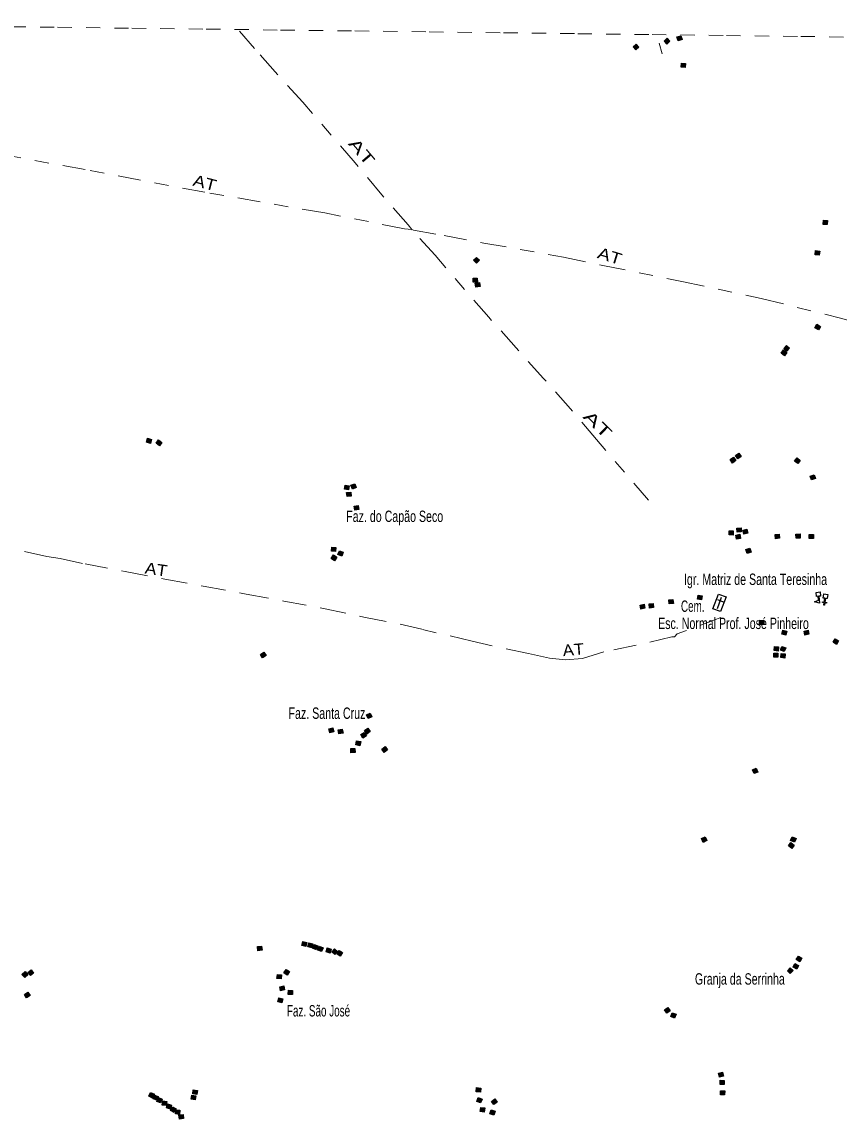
# Model space of a CAD drawing. Extents: x 679 to 705, y 7427.4 to 7455.4.
# Drawn here: x 682.26 to 688.01, y 7447.66 to 7455.38 of the extents above; entities that cross this region are included whole.
import ezdxf
from ezdxf.enums import TextEntityAlignment as Align

# ---------------------------------------------------------------- set-up
doc = ezdxf.new("R2010")
doc.units = 0
doc.header["$LTSCALE"] = 0.032
doc.linetypes.add('DOT_DASHED', pattern=[7.7, 5, -1.2, 0.3, -1.2])
doc.linetypes.add('SHORT_DASHED', pattern=[2.7, 1.5, -1.2])
for name, color, linetype, lineweight in [('2', 7, 'Continuous', 25), ('20', 7, 'Continuous', 25), ('4', 7, 'Continuous', 25), ('51', 7, 'Continuous', 13), ('56', 7, 'DOT_DASHED', 13), ('58', 7, 'SHORT_DASHED', 13), ('6', 7, 'Continuous', 25)]:
    doc.layers.add(name, color=color, linetype=linetype, lineweight=lineweight)
doc.layers.add('61', color=7, linetype='Continuous')

msp = doc.modelspace()

# ---------------------------------------------------------------- hatches: boundary and pattern name
at = {"layer": '2'}
for points in [[(686.9034, 7455.2523), (686.876, 7455.243), (686.8667, 7455.2705), (686.8942, 7455.2798)], [(686.5807, 7455.2205), (686.6, 7455.1989), (686.5783, 7455.1796), (686.559, 7455.2012)], [(686.7985, 7455.2617), (686.8181, 7455.2404), (686.7968, 7455.2207), (686.7771, 7455.2421)], [(686.9275, 7455.0845), (686.9257, 7455.0556), (686.8968, 7455.0573), (686.8985, 7455.0863)], [(687.9276, 7453.9788), (687.9256, 7453.9499), (687.8967, 7453.9519), (687.8987, 7453.9808)], [(685.457, 7453.7197), (685.4775, 7453.6991), (685.457, 7453.6786), (685.4365, 7453.6992)], [(687.8725, 7453.7642), (687.8695, 7453.7353), (687.8407, 7453.7384), (687.8437, 7453.7672)], [(685.4622, 7453.5745), (685.463, 7453.5455), (685.434, 7453.5448), (685.4332, 7453.5738)], [(685.4765, 7453.5433), (685.4814, 7453.5147), (685.4528, 7453.5099), (685.4479, 7453.5384)], [(687.8529, 7453.2493), (687.8778, 7453.2344), (687.8628, 7453.2095), (687.838, 7453.2244)], [(687.6183, 7453.0685), (687.6415, 7453.0511), (687.6241, 7453.0279), (687.6009, 7453.0453)], [(687.6385, 7453.0996), (687.6601, 7453.0802), (687.6407, 7453.0587), (687.6191, 7453.078)], [(683.1418, 7452.4465), (683.1699, 7452.439), (683.1624, 7452.411), (683.1344, 7452.4185)], [(683.2191, 7452.4347), (683.2419, 7452.4169), (683.2241, 7452.394), (683.2012, 7452.4118)], [(687.3033, 7452.3419), (687.3192, 7452.3176), (687.295, 7452.3017), (687.2791, 7452.3259)], [(687.2655, 7452.3132), (687.2824, 7452.2896), (687.2588, 7452.2727), (687.2419, 7452.2963)], [(687.7129, 7452.3091), (687.7355, 7452.2909), (687.7172, 7452.2684), (687.6947, 7452.2866)], [(687.8327, 7452.19), (687.8419, 7452.1625), (687.8143, 7452.1533), (687.8052, 7452.1808)], [(684.5599, 7452.1126), (684.5561, 7452.0838), (684.5274, 7452.0875), (684.5311, 7452.1163)], [(684.5991, 7452.1268), (684.6103, 7452.1), (684.5836, 7452.0888), (684.5723, 7452.1156)], [(684.5708, 7452.0686), (684.5744, 7452.0398), (684.5456, 7452.0362), (684.542, 7452.065)], [(684.6231, 7451.9747), (684.6287, 7451.9462), (684.6003, 7451.9406), (684.5947, 7451.9691)], [(687.2641, 7451.7949), (687.2634, 7451.766), (687.2344, 7451.7667), (687.2351, 7451.7957)], [(687.3185, 7451.8166), (687.3201, 7451.7876), (687.2912, 7451.7861), (687.2896, 7451.815)], [(687.3592, 7451.8061), (687.3654, 7451.7778), (687.3371, 7451.7716), (687.3309, 7451.7999)], [(687.3102, 7451.7709), (687.3158, 7451.7425), (687.2874, 7451.7368), (687.2817, 7451.7652)], [(687.5875, 7451.7717), (687.5901, 7451.7429), (687.5613, 7451.7402), (687.5586, 7451.7691)], [(687.7341, 7451.7734), (687.7357, 7451.7444), (687.7068, 7451.7428), (687.7052, 7451.7718)], [(687.8275, 7451.7706), (687.8275, 7451.7416), (687.7985, 7451.7416), (687.7985, 7451.7706)], [(684.4671, 7451.6784), (684.4639, 7451.6496), (684.435, 7451.6528), (684.4382, 7451.6816)], [(684.4913, 7451.6549), (684.5184, 7451.6444), (684.5079, 7451.6174), (684.4809, 7451.6278)], [(687.3796, 7451.6735), (687.3895, 7451.6463), (687.3623, 7451.6363), (687.3523, 7451.6635)], [(684.4504, 7451.6254), (684.4743, 7451.609), (684.4578, 7451.5851), (684.4339, 7451.6015)], [(687.0443, 7451.3383), (687.0403, 7451.3095), (687.0116, 7451.3135), (687.0156, 7451.3422)], [(686.6357, 7451.2791), (686.6424, 7451.2509), (686.6141, 7451.2443), (686.6075, 7451.2725)], [(686.6996, 7451.2838), (686.7023, 7451.2549), (686.6735, 7451.2522), (686.6708, 7451.2811)], [(686.8394, 7451.3127), (686.8424, 7451.2839), (686.8135, 7451.2809), (686.8105, 7451.3097)], [(687.479, 7451.1649), (687.4783, 7451.1359), (687.4493, 7451.1366), (687.45, 7451.1656)], [(687.6402, 7451.0892), (687.6328, 7451.0612), (687.6047, 7451.0687), (687.6122, 7451.0967)], [(687.7904, 7451.0956), (687.7962, 7451.0672), (687.7678, 7451.0614), (687.762, 7451.0898)], [(687.9804, 7451.0362), (688.0055, 7451.0217), (687.9911, 7450.9966), (687.9659, 7451.011)], [(683.9593, 7450.9419), (683.9753, 7450.9177), (683.9512, 7450.9017), (683.9351, 7450.9258)], [(687.583, 7450.9784), (687.5798, 7450.9496), (687.551, 7450.9527), (687.5541, 7450.9815)], [(687.6327, 7450.9726), (687.6231, 7450.9453), (687.5957, 7450.9549), (687.6054, 7450.9823)], [(687.5772, 7450.9349), (687.5777, 7450.9059), (687.5487, 7450.9054), (687.5482, 7450.9344)], [(687.63, 7450.9293), (687.6275, 7450.9004), (687.5986, 7450.9029), (687.6011, 7450.9318)], [(684.7088, 7450.5122), (684.7206, 7450.4857), (684.6942, 7450.4738), (684.6823, 7450.5003)], [(684.4456, 7450.4086), (684.4526, 7450.3805), (684.4245, 7450.3734), (684.4174, 7450.4016)], [(684.5121, 7450.3999), (684.5172, 7450.3714), (684.4886, 7450.3663), (684.4835, 7450.3948)], [(684.6923, 7450.4062), (684.7091, 7450.3826), (684.6855, 7450.3657), (684.6687, 7450.3893)], [(684.6669, 7450.3771), (684.6815, 7450.3521), (684.6565, 7450.3375), (684.6419, 7450.3625)], [(684.6001, 7450.2644), (684.6016, 7450.2355), (684.5727, 7450.2339), (684.5711, 7450.2629)], [(684.6415, 7450.312), (684.636, 7450.2835), (684.6076, 7450.289), (684.613, 7450.3174)], [(684.8135, 7450.277), (684.8303, 7450.2534), (684.8067, 7450.2365), (684.7899, 7450.2601)], [(687.4258, 7450.125), (687.437, 7450.0982), (687.4102, 7450.087), (687.399, 7450.1138)], [(687.0661, 7449.6419), (687.0786, 7449.6157), (687.0525, 7449.6032), (687.0399, 7449.6294)], [(687.6795, 7449.6432), (687.7059, 7449.6312), (687.6939, 7449.6048), (687.6675, 7449.6167)], [(687.6689, 7449.6011), (687.6924, 7449.5841), (687.6754, 7449.5606), (687.6519, 7449.5776)], [(683.9441, 7448.8729), (683.9471, 7448.844), (683.9183, 7448.841), (683.9153, 7448.8699)], [(684.2342, 7448.9058), (684.2624, 7448.8993), (684.2559, 7448.8711), (684.2276, 7448.8776)], [(684.2765, 7448.8968), (684.3044, 7448.8887), (684.2963, 7448.8609), (684.2685, 7448.869)], [(684.3131, 7448.8848), (684.3402, 7448.8744), (684.3297, 7448.8473), (684.3027, 7448.8578)], [(684.3502, 7448.8723), (684.377, 7448.8612), (684.3659, 7448.8344), (684.3391, 7448.8455)], [(684.4057, 7448.8601), (684.4335, 7448.8521), (684.4255, 7448.8242), (684.3976, 7448.8323)], [(684.4571, 7448.8547), (684.4786, 7448.8352), (684.4591, 7448.8137), (684.4376, 7448.8331)], [(684.4891, 7448.843), (684.5134, 7448.8273), (684.4977, 7448.8029), (684.4733, 7448.8187)], [(687.7225, 7448.803), (687.7473, 7448.7881), (687.7324, 7448.7632), (687.7076, 7448.7781)], [(682.3216, 7448.7062), (682.3394, 7448.6833), (682.3165, 7448.6655), (682.2987, 7448.6884)], [(684.1158, 7448.709), (684.1403, 7448.6935), (684.1248, 7448.669), (684.1003, 7448.6845)], [(687.6646, 7448.7207), (687.6855, 7448.7006), (687.6654, 7448.6797), (687.6445, 7448.6998)], [(687.6969, 7448.7498), (687.723, 7448.7372), (687.7103, 7448.7111), (687.6843, 7448.7238)], [(682.2787, 7448.6935), (682.2982, 7448.6721), (682.2767, 7448.6526), (682.2572, 7448.674)], [(684.0842, 7448.6706), (684.081, 7448.6417), (684.0522, 7448.6449), (684.0554, 7448.6738)], [(682.2983, 7448.5493), (682.3142, 7448.525), (682.2899, 7448.5091), (682.274, 7448.5334)], [(684.1007, 7448.593), (684.106, 7448.5645), (684.0775, 7448.5592), (684.0722, 7448.5877)], [(684.1625, 7448.561), (684.161, 7448.532), (684.132, 7448.5335), (684.1335, 7448.5625)], [(684.0929, 7448.5024), (684.0862, 7448.4742), (684.058, 7448.4808), (684.0646, 7448.5091)], [(686.804, 7448.4409), (686.8205, 7448.4171), (686.7967, 7448.4005), (686.7802, 7448.4243)], [(686.8341, 7448.4042), (686.8612, 7448.3939), (686.8509, 7448.3668), (686.8238, 7448.3772)], [(687.1883, 7447.9855), (687.1956, 7447.9575), (687.1675, 7447.9501), (687.1602, 7447.9782)], [(687.2005, 7447.928), (687.1999, 7447.899), (687.1709, 7447.8997), (687.1715, 7447.9286)], [(683.4633, 7447.8613), (683.4919, 7447.8569), (683.4876, 7447.8283), (683.4589, 7447.8326)], [(685.4864, 7447.8743), (685.4835, 7447.8454), (685.4546, 7447.8483), (685.4575, 7447.8771)], [(687.2037, 7447.8546), (687.2031, 7447.8256), (687.1741, 7447.8263), (687.1747, 7447.8553)], [(683.1889, 7447.8303), (683.1767, 7447.804), (683.1504, 7447.8163), (683.1627, 7447.8425)], [(683.217, 7447.815), (683.2069, 7447.7879), (683.1797, 7447.798), (683.1899, 7447.8252)], [(683.2444, 7447.7957), (683.2327, 7447.7691), (683.2062, 7447.7808), (683.2178, 7447.8073)], [(683.2766, 7447.7798), (683.273, 7447.751), (683.2443, 7447.7546), (683.2478, 7447.7834)], [(683.4529, 7447.8249), (683.4815, 7447.8203), (683.477, 7447.7917), (683.4483, 7447.7963)], [(685.4956, 7447.7963), (685.485, 7447.7694), (685.458, 7447.78), (685.4686, 7447.807)], [(685.5858, 7447.798), (685.603, 7447.7746), (685.5796, 7447.7575), (685.5625, 7447.7808)], [(683.3101, 7447.7542), (683.3019, 7447.7263), (683.2741, 7447.7345), (683.2822, 7447.7623)], [(683.3422, 7447.7269), (683.3278, 7447.7017), (683.3026, 7447.7161), (683.317, 7447.7413)], [(683.3688, 7447.718), (683.3659, 7447.6892), (683.3371, 7447.6921), (683.3399, 7447.7209)], [(685.5157, 7447.7342), (685.5115, 7447.7055), (685.4828, 7447.7097), (685.487, 7447.7384)], [(685.5879, 7447.7111), (685.5786, 7447.6837), (685.5511, 7447.693), (685.5604, 7447.7204)], [(683.3908, 7447.6893), (683.3953, 7447.6606), (683.3667, 7447.6561), (683.3621, 7447.6848)]]:
    msp.add_hatch(color=256, dxfattribs=at).paths.add_polyline_path(points)

# ---------------------------------------------------------------- linework, layer by layer
for points in [[(686.9034, 7455.2523), (686.876, 7455.243), (686.8667, 7455.2705), (686.8942, 7455.2798)], [(686.5807, 7455.2205), (686.6, 7455.1989), (686.5783, 7455.1796), (686.559, 7455.2012)], [(686.7985, 7455.2617), (686.8181, 7455.2404), (686.7968, 7455.2207), (686.7771, 7455.2421)], [(686.9275, 7455.0845), (686.9257, 7455.0556), (686.8968, 7455.0573), (686.8985, 7455.0863)], [(687.9276, 7453.9788), (687.9256, 7453.9499), (687.8967, 7453.9519), (687.8987, 7453.9808)], [(685.457, 7453.7197), (685.4775, 7453.6991), (685.457, 7453.6786), (685.4365, 7453.6992)], [(687.8725, 7453.7642), (687.8695, 7453.7353), (687.8407, 7453.7384), (687.8437, 7453.7672)], [(685.4622, 7453.5745), (685.463, 7453.5455), (685.434, 7453.5448), (685.4332, 7453.5738)], [(685.4765, 7453.5433), (685.4814, 7453.5147), (685.4528, 7453.5099), (685.4479, 7453.5384)], [(687.8529, 7453.2493), (687.8778, 7453.2344), (687.8628, 7453.2095), (687.838, 7453.2244)], [(687.6183, 7453.0685), (687.6415, 7453.0511), (687.6241, 7453.0279), (687.6009, 7453.0453)], [(687.6385, 7453.0996), (687.6601, 7453.0802), (687.6407, 7453.0587), (687.6191, 7453.078)], [(683.1418, 7452.4465), (683.1699, 7452.439), (683.1624, 7452.411), (683.1344, 7452.4185)], [(683.2191, 7452.4347), (683.2419, 7452.4169), (683.2241, 7452.394), (683.2012, 7452.4118)], [(687.3033, 7452.3419), (687.3192, 7452.3176), (687.295, 7452.3017), (687.2791, 7452.3259)], [(687.2655, 7452.3132), (687.2824, 7452.2896), (687.2588, 7452.2727), (687.2419, 7452.2963)], [(687.7129, 7452.3091), (687.7355, 7452.2909), (687.7172, 7452.2684), (687.6947, 7452.2866)], [(687.8327, 7452.19), (687.8419, 7452.1625), (687.8143, 7452.1533), (687.8052, 7452.1808)], [(684.5599, 7452.1126), (684.5561, 7452.0838), (684.5274, 7452.0875), (684.5311, 7452.1163)], [(684.5991, 7452.1268), (684.6103, 7452.1), (684.5836, 7452.0888), (684.5723, 7452.1156)], [(684.5708, 7452.0686), (684.5744, 7452.0398), (684.5456, 7452.0362), (684.542, 7452.065)], [(684.6231, 7451.9747), (684.6287, 7451.9462), (684.6003, 7451.9406), (684.5947, 7451.9691)], [(687.2641, 7451.7949), (687.2634, 7451.766), (687.2344, 7451.7667), (687.2351, 7451.7957)], [(687.3185, 7451.8166), (687.3201, 7451.7876), (687.2912, 7451.7861), (687.2896, 7451.815)], [(687.3592, 7451.8061), (687.3654, 7451.7778), (687.3371, 7451.7716), (687.3309, 7451.7999)], [(687.3102, 7451.7709), (687.3158, 7451.7425), (687.2874, 7451.7368), (687.2817, 7451.7652)], [(687.5875, 7451.7717), (687.5901, 7451.7429), (687.5613, 7451.7402), (687.5586, 7451.7691)], [(687.7341, 7451.7734), (687.7357, 7451.7444), (687.7068, 7451.7428), (687.7052, 7451.7718)], [(687.8275, 7451.7706), (687.8275, 7451.7416), (687.7985, 7451.7416), (687.7985, 7451.7706)], [(684.4671, 7451.6784), (684.4639, 7451.6496), (684.435, 7451.6528), (684.4382, 7451.6816)], [(684.4913, 7451.6549), (684.5184, 7451.6444), (684.5079, 7451.6174), (684.4809, 7451.6278)], [(687.3796, 7451.6735), (687.3895, 7451.6463), (687.3623, 7451.6363), (687.3523, 7451.6635)], [(684.4504, 7451.6254), (684.4743, 7451.609), (684.4578, 7451.5851), (684.4339, 7451.6015)], [(687.0443, 7451.3383), (687.0403, 7451.3095), (687.0116, 7451.3135), (687.0156, 7451.3422)], [(686.6357, 7451.2791), (686.6424, 7451.2509), (686.6141, 7451.2443), (686.6075, 7451.2725)], [(686.6996, 7451.2838), (686.7023, 7451.2549), (686.6735, 7451.2522), (686.6708, 7451.2811)], [(686.8394, 7451.3127), (686.8424, 7451.2839), (686.8135, 7451.2809), (686.8105, 7451.3097)], [(687.479, 7451.1649), (687.4783, 7451.1359), (687.4493, 7451.1366), (687.45, 7451.1656)], [(687.6402, 7451.0892), (687.6328, 7451.0612), (687.6047, 7451.0687), (687.6122, 7451.0967)], [(687.7904, 7451.0956), (687.7962, 7451.0672), (687.7678, 7451.0614), (687.762, 7451.0898)], [(687.9804, 7451.0362), (688.0055, 7451.0217), (687.9911, 7450.9966), (687.9659, 7451.011)], [(683.9593, 7450.9419), (683.9753, 7450.9177), (683.9512, 7450.9017), (683.9351, 7450.9258)], [(687.583, 7450.9784), (687.5798, 7450.9496), (687.551, 7450.9527), (687.5541, 7450.9815)], [(687.6327, 7450.9726), (687.6231, 7450.9453), (687.5957, 7450.9549), (687.6054, 7450.9823)], [(687.5772, 7450.9349), (687.5777, 7450.9059), (687.5487, 7450.9054), (687.5482, 7450.9344)], [(687.63, 7450.9293), (687.6275, 7450.9004), (687.5986, 7450.9029), (687.6011, 7450.9318)], [(684.7088, 7450.5122), (684.7206, 7450.4857), (684.6942, 7450.4738), (684.6823, 7450.5003)], [(684.4456, 7450.4086), (684.4526, 7450.3805), (684.4245, 7450.3734), (684.4174, 7450.4016)], [(684.5121, 7450.3999), (684.5172, 7450.3714), (684.4886, 7450.3663), (684.4835, 7450.3948)], [(684.6923, 7450.4062), (684.7091, 7450.3826), (684.6855, 7450.3657), (684.6687, 7450.3893)], [(684.6669, 7450.3771), (684.6815, 7450.3521), (684.6565, 7450.3375), (684.6419, 7450.3625)], [(684.6001, 7450.2644), (684.6016, 7450.2355), (684.5727, 7450.2339), (684.5711, 7450.2629)], [(684.6415, 7450.312), (684.636, 7450.2835), (684.6076, 7450.289), (684.613, 7450.3174)], [(684.8135, 7450.277), (684.8303, 7450.2534), (684.8067, 7450.2365), (684.7899, 7450.2601)], [(687.4258, 7450.125), (687.437, 7450.0982), (687.4102, 7450.087), (687.399, 7450.1138)], [(687.0661, 7449.6419), (687.0786, 7449.6157), (687.0525, 7449.6032), (687.0399, 7449.6294)], [(687.6795, 7449.6432), (687.7059, 7449.6312), (687.6939, 7449.6048), (687.6675, 7449.6167)], [(687.6689, 7449.6011), (687.6924, 7449.5841), (687.6754, 7449.5606), (687.6519, 7449.5776)], [(683.9441, 7448.8729), (683.9471, 7448.844), (683.9183, 7448.841), (683.9153, 7448.8699)], [(684.2342, 7448.9058), (684.2624, 7448.8993), (684.2559, 7448.8711), (684.2276, 7448.8776)], [(684.2765, 7448.8968), (684.3044, 7448.8887), (684.2963, 7448.8609), (684.2685, 7448.869)], [(684.3131, 7448.8848), (684.3402, 7448.8744), (684.3297, 7448.8473), (684.3027, 7448.8578)], [(684.3502, 7448.8723), (684.377, 7448.8612), (684.3659, 7448.8344), (684.3391, 7448.8455)], [(684.4057, 7448.8601), (684.4335, 7448.8521), (684.4255, 7448.8242), (684.3976, 7448.8323)], [(684.4571, 7448.8547), (684.4786, 7448.8352), (684.4591, 7448.8137), (684.4376, 7448.8331)], [(684.4891, 7448.843), (684.5134, 7448.8273), (684.4977, 7448.8029), (684.4733, 7448.8187)], [(687.7225, 7448.803), (687.7473, 7448.7881), (687.7324, 7448.7632), (687.7076, 7448.7781)], [(682.3216, 7448.7062), (682.3394, 7448.6833), (682.3165, 7448.6655), (682.2987, 7448.6884)], [(684.1158, 7448.709), (684.1403, 7448.6935), (684.1248, 7448.669), (684.1003, 7448.6845)], [(687.6646, 7448.7207), (687.6855, 7448.7006), (687.6654, 7448.6797), (687.6445, 7448.6998)], [(687.6969, 7448.7498), (687.723, 7448.7372), (687.7103, 7448.7111), (687.6843, 7448.7238)], [(682.2787, 7448.6935), (682.2982, 7448.6721), (682.2767, 7448.6526), (682.2572, 7448.674)], [(684.0842, 7448.6706), (684.081, 7448.6417), (684.0522, 7448.6449), (684.0554, 7448.6738)], [(682.2983, 7448.5493), (682.3142, 7448.525), (682.2899, 7448.5091), (682.274, 7448.5334)], [(684.1007, 7448.593), (684.106, 7448.5645), (684.0775, 7448.5592), (684.0722, 7448.5877)], [(684.1625, 7448.561), (684.161, 7448.532), (684.132, 7448.5335), (684.1335, 7448.5625)], [(684.0929, 7448.5024), (684.0862, 7448.4742), (684.058, 7448.4808), (684.0646, 7448.5091)], [(686.804, 7448.4409), (686.8205, 7448.4171), (686.7967, 7448.4005), (686.7802, 7448.4243)], [(686.8341, 7448.4042), (686.8612, 7448.3939), (686.8509, 7448.3668), (686.8238, 7448.3772)], [(687.1883, 7447.9855), (687.1956, 7447.9575), (687.1675, 7447.9501), (687.1602, 7447.9782)], [(687.2005, 7447.928), (687.1999, 7447.899), (687.1709, 7447.8997), (687.1715, 7447.9286)], [(683.4633, 7447.8613), (683.4919, 7447.8569), (683.4876, 7447.8283), (683.4589, 7447.8326)], [(685.4864, 7447.8743), (685.4835, 7447.8454), (685.4546, 7447.8483), (685.4575, 7447.8771)], [(687.2037, 7447.8546), (687.2031, 7447.8256), (687.1741, 7447.8263), (687.1747, 7447.8553)], [(683.1889, 7447.8303), (683.1767, 7447.804), (683.1504, 7447.8163), (683.1627, 7447.8425)], [(683.217, 7447.815), (683.2069, 7447.7879), (683.1797, 7447.798), (683.1899, 7447.8252)], [(683.2444, 7447.7957), (683.2327, 7447.7691), (683.2062, 7447.7808), (683.2178, 7447.8073)], [(683.2766, 7447.7798), (683.273, 7447.751), (683.2443, 7447.7546), (683.2478, 7447.7834)], [(683.4529, 7447.8249), (683.4815, 7447.8203), (683.477, 7447.7917), (683.4483, 7447.7963)], [(685.4956, 7447.7963), (685.485, 7447.7694), (685.458, 7447.78), (685.4686, 7447.807)], [(685.5858, 7447.798), (685.603, 7447.7746), (685.5796, 7447.7575), (685.5625, 7447.7808)], [(683.3101, 7447.7542), (683.3019, 7447.7263), (683.2741, 7447.7345), (683.2822, 7447.7623)], [(683.3422, 7447.7269), (683.3278, 7447.7017), (683.3026, 7447.7161), (683.317, 7447.7413)], [(683.3688, 7447.718), (683.3659, 7447.6892), (683.3371, 7447.6921), (683.3399, 7447.7209)], [(685.5157, 7447.7342), (685.5115, 7447.7055), (685.4828, 7447.7097), (685.487, 7447.7384)], [(685.5879, 7447.7111), (685.5786, 7447.6837), (685.5511, 7447.693), (685.5604, 7447.7204)], [(683.3908, 7447.6893), (683.3953, 7447.6606), (683.3667, 7447.6561), (683.3621, 7447.6848)]]:
    msp.add_lwpolyline(points, close=True, dxfattribs=at)
at = {"layer": '20'}
for p, q in [((687.1523, 7451.2499), (687.1821, 7451.328)), ((687.1528, 7451.3117), (687.1927, 7451.2965))]:
    msp.add_line(p, q, dxfattribs=at)
msp.add_lwpolyline([(687.1598, 7451.3501), (687.213, 7451.3298), (687.1737, 7451.2268), (687.1205, 7451.2471)], close=True, dxfattribs=at)
at = {"layer": '4'}
for points in [[(687.8667, 7451.335), (687.8713, 7451.2868), (687.8365, 7451.2952), (687.8643, 7451.3086), (687.8619, 7451.3346)], [(687.8619, 7451.3346), (687.8498, 7451.3334), (687.8471, 7451.3623), (687.8759, 7451.365), (687.8787, 7451.3362), (687.8667, 7451.335)]]:
    msp.add_lwpolyline(points, dxfattribs=at)
at = {"layer": '51'}
msp.add_line((686.7632, 7455.1518), (686.7424, 7455.2275), dxfattribs=at)
at = {"layer": '56'}
for points in [[(685.0003, 7453.9163), (684.9755, 7453.9478), (684.7911, 7454.1603), (684.6036, 7454.384), (684.2334, 7454.8116), (684.0398, 7455.0254), (683.8942, 7455.1903), (683.7785, 7455.3231)], [(685.0003, 7453.9163), (684.9504, 7453.9212), (684.3878, 7454.0322), (683.544, 7454.178), (682.7017, 7454.3372), (681.8642, 7454.489), (681.0122, 7454.6425), (680.6188, 7454.7152), (680.325, 7454.7692), (680.1415, 7454.8044), (679.9557, 7454.8414), (679.4646, 7454.9339), (679.3645, 7454.9524)], [(686.6669, 7452.0102), (686.3005, 7452.4384), (686.1181, 7452.6528), (685.9279, 7452.8678), (685.7356, 7453.0822), (685.5432, 7453.2984), (685.1644, 7453.7347), (685.0038, 7453.9133), (685.0003, 7453.9163)], [(685.0003, 7453.9163), (685.013, 7453.9116), (685.2285, 7453.8725), (685.5082, 7453.8208), (686.0678, 7453.7211), (686.3459, 7453.6633), (686.9027, 7453.5508), (687.4611, 7453.431), (688.0181, 7453.2912), (688.5601, 7453.1499), (689.1094, 7453.0028), (689.6616, 7452.8679), (690.2157, 7452.7249), (690.7571, 7452.5778), (691.3047, 7452.426), (691.5859, 7452.3484), (692.4067, 7452.1254), (693.1904, 7451.9134), (693.214, 7451.907)], [(682.2751, 7451.65), (682.4312, 7451.6147), (682.5269, 7451.6012), (682.7017, 7451.5623), (682.9831, 7451.5099), (683.2632, 7451.4559), (683.5329, 7451.4069), (683.8348, 7451.3498), (684.1014, 7451.301), (684.3797, 7451.2491), (684.6629, 7451.1878), (684.9492, 7451.1318), (685.071, 7451.1031)], [(687.1772, 7451.1862), (686.8701, 7451.0702), (686.8502, 7451.0497)], [(686.8502, 7451.0497), (686.8321, 7451.0484), (686.5805, 7450.9909), (686.3526, 7450.9436), (686.2018, 7450.8979), (686.0833, 7450.8869), (685.9699, 7450.8987), (685.8223, 7450.9326), (685.5676, 7450.9854), (685.4265, 7451.0184), (685.071, 7451.1031)]]:
    msp.add_lwpolyline(points, dxfattribs=at)
at = {"layer": '58'}
msp.add_lwpolyline([(679.3696, 7455.3764), (679.8926, 7455.3701), (680.4157, 7455.3638), (680.9388, 7455.3576), (681.4618, 7455.3512), (681.9849, 7455.3449), (682.5079, 7455.3386), (683.031, 7455.3322), (683.5541, 7455.3258), (684.0771, 7455.3194), (684.6002, 7455.313), (685.1233, 7455.3066), (685.6463, 7455.3001), (686.1694, 7455.2937), (686.6925, 7455.2872), (687.2155, 7455.2807), (687.7386, 7455.2741), (688.2617, 7455.2676)], dxfattribs=at)
at = {"layer": '6'}
for points in [[(687.9083, 7451.3206), (687.8963, 7451.3222), (687.9003, 7451.3509), (687.929, 7451.3469), (687.9251, 7451.3182), (687.9131, 7451.3199)], [(687.9131, 7451.3199), (687.9093, 7451.293), (687.9213, 7451.2914), (687.9206, 7451.2865), (687.9087, 7451.2882), (687.9064, 7451.272), (687.9017, 7451.2726), (687.9039, 7451.2889), (687.8919, 7451.2905), (687.8926, 7451.2954), (687.9046, 7451.2937), (687.9083, 7451.3206)]]:
    msp.add_lwpolyline(points, dxfattribs=at)

# ---------------------------------------------------------------- texts
at = {"layer": '61'}
for rotation, width, p in [(310.309, 1.55, (684.6182, 7454.4367)), (345.314, 1.2, (683.5341, 7454.2053)), (342.784, 1.25, (686.3828, 7453.6912)), (315.815, 1.65, (686.2821, 7452.515)), (351.698, 1.15, (683.1959, 7451.4847)), (4.901, 1.1, (686.1416, 7450.9195))]:
    msp.add_text('AT', height=0.08, rotation=rotation, dxfattribs=dict(at, width=width)).set_placement(p, align=Align.CENTER)
for s, width, p in [('Faz. do Capão Seco', 0.7, (684.5394, 7451.8577)), ('Igr. Matriz de Santa Teresinha', 0.7, (686.917, 7451.4146)), ('Cem.', 0.65, (686.8956, 7451.2253)), ('Esc. Normal Prof. José Pinheiro ', 0.7, (686.7347, 7451.1044)), ('Faz. Santa Cruz', 0.7, (684.1334, 7450.4722)), ('Granja da Serrinha', 0.7, (686.9939, 7448.6022)), ('Faz. São José', 0.65, (684.1223, 7448.378))]:
    msp.add_text(s, height=0.08, dxfattribs=dict(at, width=width)).set_placement(p)

doc.saveas('drawing.dxf')
